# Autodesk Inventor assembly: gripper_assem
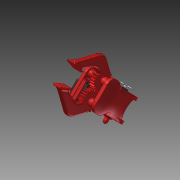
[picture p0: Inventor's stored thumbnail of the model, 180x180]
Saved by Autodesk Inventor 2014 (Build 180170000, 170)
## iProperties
Created: 2014-04
Part Number: gripper_assem
Document SubType Name: Assembly
Designer: t_emanb
Author: t_emanb
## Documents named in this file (8)
- C:\Users\t_emanb\Documents\3D printed arm\4th version\gripper_assem.iam
- C:\Users\t_emanb\Documents\3D printed arm\stock parts\microservo_assem.iam
- C:\Users\t_emanb\Documents\3D printed arm\4th version\upper_pin.ipt
- C:\Users\t_emanb\Documents\3D printed arm\4th version\upper_servo.ipt
- C:\Users\t_emanb\Documents\3D printed arm\4th version\gripper_gearMirror.ipt
- C:\Users\t_emanb\Documents\3D printed arm\4th version\gripper_base2.ipt
- C:\Users\t_emanb\Documents\3D printed arm\4th version\gripper_base.ipt
- C:\Users\t_emanb\Documents\3D printed arm\4th version\gripper_gearServo.ipt
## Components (8 placed, 6 different names)
1. upper_servo:1 — Mate:16, Flush:5, Mate:29, Mate:36, Mate:43, Mate:44
2. upper_pin:1 — Flush:1, Flush:2, Mate:17, Flush:3, Mate:26, Mate:35
3. Spur Gear1:2 — Mate:19, Mate:20
4. microservo_assem:2 [sub-assembly] — Mate:16, Mate:43, Mate:44
5. gripper_base2:1 — Flush:1, Flush:2, Mate:17, Mate:19, Mate:20, Mate:45, Mate:46, Mate:47
6. gripper_base:1 — Flush:3, Mate:26, Flush:5, Mate:29, Mate:35, Mate:36
7. Spur Gear1:3 — Mate:40, Mate:41, Mate:42
8. microservo_assem:3 [sub-assembly] — Mate:40, Mate:41, Mate:42, Mate:45, Mate:46, Mate:47
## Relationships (20: Mate 16, Flush 4)
- Mate:16: upper_servo:1 ↔ microservo_assem:2
- Flush:1: upper_pin:1 ↔ gripper_base2:1
- Flush:2: upper_pin:1 ↔ gripper_base2:1
- Mate:17: upper_pin:1 ↔ gripper_base2:1
- Mate:19: Spur Gear1:2 ↔ gripper_base2:1
- Mate:20: Spur Gear1:2 ↔ gripper_base2:1
- Flush:3: upper_pin:1 ↔ gripper_base:1
- Mate:26: upper_pin:1 ↔ gripper_base:1
- Flush:5: upper_servo:1 ↔ gripper_base:1
- Mate:29: upper_servo:1 ↔ gripper_base:1
- Mate:35: upper_pin:1 ↔ gripper_base:1
- Mate:36: upper_servo:1 ↔ gripper_base:1
- Mate:40: Spur Gear1:3 ↔ microservo_assem:3
- Mate:41: Spur Gear1:3 ↔ microservo_assem:3
- Mate:42: Spur Gear1:3 ↔ microservo_assem:3
- Mate:43: upper_servo:1 ↔ microservo_assem:2
- Mate:44: upper_servo:1 ↔ microservo_assem:2
- Mate:45: gripper_base2:1 ↔ microservo_assem:3
- Mate:46: gripper_base2:1 ↔ microservo_assem:3
- Mate:47: gripper_base2:1 ↔ microservo_assem:3
